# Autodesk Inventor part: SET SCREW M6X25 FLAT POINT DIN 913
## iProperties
IsCustomPart: 1
Created: 2006-02
Part Number: SET SCREW M6X25 FLAT POINT DIN 913
Material: Steel, Mild
Description: Hexagon Socket Set Screw
Document SubType Name: Modeling
Standard: DIN 913
Designer: Andy Moles
Standards Organization: DIN
Language: en-US
Size Designation: M6 x 25
Categories: <MemberInstance><Categories><Category DisplayName="Fasteners" InternalName="e4da775c-781d-43d5-af7c-5136215cf5a6" Mnemonic="FSTN"><Category DisplayName="Bolts"
Density: 7.86 g/cm^3
Mass: 5.26552 g
Surface Area: 5.51755 cm^2
Volume: 0.669913 cm^3
Author: Andy Moles
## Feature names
1. Body [Revolution]
2. Slot [Extrusion]
3. Chamfer1
4. Chamfer2
